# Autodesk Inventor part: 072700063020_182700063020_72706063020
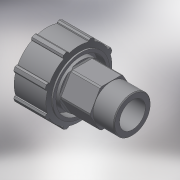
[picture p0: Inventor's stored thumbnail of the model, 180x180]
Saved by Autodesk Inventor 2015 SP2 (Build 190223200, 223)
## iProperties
Created: 2017-04
Part Number: 072700063020_182700063020_72706063020
Material: Generic
Description: PLASSON BRASS THREADED ADAPTOR 63-2"
Document SubType Name: Modeling
Designer: KIM
Density: 1 g/cm^3
Appearance: Default
Author: KIM
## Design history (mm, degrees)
derived "07270.ipt"
feature "Solid1::07270.ipt"
tag "TaggingFeature1"
body "Solid1"
other parameters: "d1" = 59.614, "d2" = 112, "d3" = 25, "d7" = 113, "d8" = 90.4, "d9" = 63, "d12" = 41.7298, "d13" = 47.6912, "d15" = 84.75, "d17" = 44.8, "d18" = 25, "d40" = 64, "d41" = 73.6, "d42" = 135 deg, "d43" = 100 deg, "d44" = 41.216, "d45" = 80.5125, "d46" = 105.09, "d47" = 35 deg, "d48" = 17.5 deg, "d50" = 0, "d52" = 360 deg, "d54" = 2.26, "d57" = 2.26, "d61" = 0, "d62" = 1.19228, "d65" = 1.78842, "d_" = 63, "R_" = 59.614, "E_" = 113, "H_" = 112, "l_2" = 25, "Wrench" = 64
